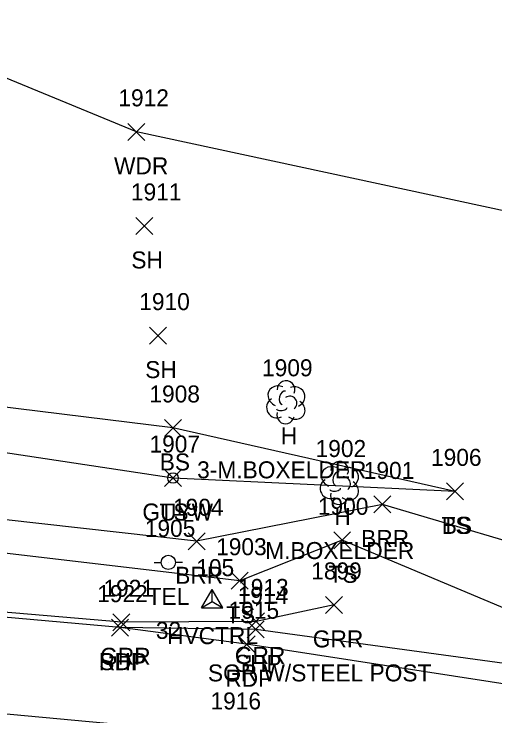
# Model space of a CAD drawing. Extents: x 1497084 to 1499861, y 734741 to 735567.
# Drawn here: x 1499623.4 to 1499680, y 735456.1 to 735538.6 of the extents above; entities that cross this region are included whole.
import ezdxf

# ---------------------------------------------------------------- set-up
doc = ezdxf.new("R2010")
doc.units = 0
for name, color, linetype in [('C_A', 7, 'Continuous'), ('C_I', 7, 'Continuous'), ('CPSM', 7, 'Continuous'), ('L_A', 7, 'Continuous'), ('L_C', 7, 'Continuous'), ('L_I', 7, 'Continuous'), ('L_TIC', 7, 'Continuous'), ('LABL', 7, 'Continuous'), ('LAWA', 7, 'Continuous'), ('LELB', 7, 'Continuous'), ('LTD', 7, 'Continuous'), ('P_A', 7, 'Continuous'), ('P_I', 7, 'Continuous'), ('P_TIC', 7, 'Continuous'), ('PET', 7, 'Continuous'), ('PRC', 7, 'Continuous'), ('PSP', 7, 'Continuous'), ('R_A', 7, 'Continuous'), ('R_C', 7, 'Continuous'), ('R_I', 7, 'Continuous'), ('R_TIC', 7, 'Continuous'), ('RGR', 7, 'Continuous'), ('U_A', 7, 'Continuous'), ('U_C', 7, 'Continuous'), ('U_I', 7, 'Continuous'), ('UP', 7, 'Continuous'), ('UPGW', 7, 'Continuous')]:
    doc.layers.add(name, color=color, linetype=linetype)

msp = doc.modelspace()

# ---------------------------------------------------------------- linework, layer by layer
at = {"layer": 'CPSM'}
for p, q in [((1499645.454, 735468.795), (1499646.704, 735470.96)), ((1499647.954, 735468.795), (1499646.704, 735470.96)), ((1499646.705, 735469.517), (1499646.704, 735470.96)), ((1499645.454, 735468.795), (1499646.705, 735469.517)), ((1499646.705, 735469.517), (1499646.705, 735469.517)), ((1499646.705, 735469.517), (1499647.954, 735468.795)), ((1499645.454, 735468.795), (1499647.954, 735468.795))]:
    msp.add_line(p, q, dxfattribs=at)
at = {"layer": 'L_TIC'}
for points in [[(1499636.791, 735523.775), (1499638.791, 735525.775)], [(1499638.791, 735523.775), (1499636.791, 735525.775)], [(1499637.702, 735512.707), (1499639.702, 735514.707)], [(1499639.702, 735512.707), (1499637.702, 735514.707)], [(1499639.338, 735499.808), (1499641.338, 735501.808)], [(1499641.338, 735499.808), (1499639.338, 735501.808)], [(1499641.088, 735488.947), (1499643.088, 735490.947)], [(1499643.088, 735488.947), (1499641.088, 735490.947)], [(1499641.096, 735483.057), (1499643.096, 735485.057)], [(1499643.096, 735483.057), (1499641.096, 735485.057)], [(1499674.288, 735481.485), (1499676.288, 735483.485)], [(1499676.288, 735481.485), (1499674.288, 735483.485)], [(1499674.288, 735481.485), (1499676.288, 735483.485)], [(1499676.288, 735481.485), (1499674.288, 735483.485)], [(1499665.752, 735479.946), (1499667.752, 735481.946)], [(1499667.752, 735479.946), (1499665.752, 735481.946)], [(1499643.867, 735475.617), (1499645.867, 735477.617)], [(1499645.867, 735475.617), (1499643.867, 735477.617)], [(1499661.005, 735475.729), (1499663.005, 735477.729)], [(1499663.005, 735475.729), (1499661.005, 735477.729)], [(1499648.942, 735470.977), (1499650.942, 735472.977)], [(1499650.942, 735470.977), (1499648.942, 735472.977)]]:
    msp.add_lwpolyline(points, dxfattribs=at)
at = {"layer": 'LABL'}
msp.add_lwpolyline([(1499689.554, 735474.192), (1499666.752, 735480.946), (1499644.867, 735476.617), (1499599.291, 735481.733), (1499595.722, 735488.498), (1499603.208, 735511.359), (1499612.735, 735535.087)], dxfattribs=at)
at = {"layer": 'LAWA'}
msp.add_lwpolyline([(1499788.738, 735496.153), (1499778.307, 735474.671), (1499770.599, 735459.37), (1499768.79, 735460.678), (1499758.938, 735469.149), (1499746.531, 735488.898), (1499729.211, 735490.085), (1499697.802, 735511.882), (1499637.791, 735524.775), (1499612.735, 735535.087), (1499594.485, 735538.631)], dxfattribs=at)
at = {"layer": 'LELB'}
for points in [[(1499675.288, 735482.485), (1499642.088, 735489.947), (1499602.834, 735494.783)], [(1499675.288, 735482.485), (1499642.096, 735484.057), (1499606.997, 735489.35)], [(1499770.599, 735459.37), (1499767.316, 735451.404), (1499753.266, 735453.514), (1499723.327, 735458.194), (1499688.043, 735465.791), (1499662.005, 735476.729), (1499649.942, 735471.977), (1499600.229, 735477.808), (1499596.973, 735472.366)]]:
    msp.add_lwpolyline(points, dxfattribs=at)
at = {"layer": 'LTD'}
for p, q in [((1499655.353, 735493.022), (1499655.353, 735493.022)), ((1499655.353, 735493.022), (1499655.353, 735493.022)), ((1499661.653, 735483.526), (1499661.653, 735483.526)), ((1499661.653, 735483.526), (1499661.653, 735483.526))]:
    msp.add_line(p, q, dxfattribs=at)
for centre in [(1499655.4, 735494.456), (1499661.699, 735484.96)]:
    msp.add_arc(centre, 1.047, 335.52715, 180.95627, dxfattribs=at)
for centre, major_axis, ratio, start_param, end_param in [((1499654.562, 735493.689), (1.21, -0.512), 0.895232, 1.570796, 4.712389), ((1499656.395, 735493.606), (-1.141, -0.483), 0.949671, 1.570796, 4.712389), ((1499655.145, 735493.481), (-0.208, -0.792), 0.645439, 3.141593, 6.283185), ((1499655.853, 735492.856), (-0.5, 0.667), 0.989748, 3.141593, 6.283185), ((1499654.27, 735492.314), (0.584, -1.042), 0.959034, 3.141593, 6.283185), ((1499656.354, 735492.189), (-1.09, 0.792), 0.841452, 1.570796, 4.712389), ((1499654.895, 735492.272), (-0.625, -0.083), 0.423636, 0, 3.141593), ((1499655.354, 735491.522), (0.265, 1.061), 0.942809, 1.570796, 4.712389), ((1499660.861, 735484.193), (1.21, -0.512), 0.895232, 1.570796, 4.712389), ((1499662.694, 735484.11), (-1.141, -0.483), 0.949671, 1.570796, 4.712389), ((1499661.444, 735483.985), (-0.208, -0.792), 0.645439, 3.141593, 6.283185), ((1499660.57, 735482.818), (0.584, -1.042), 0.959034, 3.141593, 6.283185), ((1499662.153, 735483.36), (-0.5, 0.667), 0.989748, 3.141593, 6.283185), ((1499662.653, 735482.693), (-1.09, 0.792), 0.841452, 1.570796, 4.712389), ((1499661.653, 735482.026), (0.265, 1.061), 0.942809, 1.570796, 4.712389), ((1499661.195, 735482.776), (-0.625, -0.083), 0.423636, 0, 3.141593)]:
    msp.add_ellipse(centre, major_axis=major_axis, ratio=ratio, start_param=start_param, end_param=end_param, dxfattribs=at)
at = {"layer": 'P_TIC'}
for points in [[(1499634.869, 735465.456), (1499636.869, 735467.456)], [(1499636.869, 735465.456), (1499634.869, 735467.456)], [(1499634.869, 735465.456), (1499636.869, 735467.456)], [(1499636.869, 735465.456), (1499634.869, 735467.456)], [(1499650.835, 735465.256), (1499652.835, 735467.256)], [(1499652.835, 735465.256), (1499650.835, 735467.256)], [(1499649.762, 735463.505), (1499651.762, 735465.505)], [(1499651.762, 735463.505), (1499649.762, 735465.505)]]:
    msp.add_lwpolyline(points, dxfattribs=at)
at = {"layer": 'PET'}
msp.add_lwpolyline([(1499846.488, 735425.23), (1499785.866, 735440.032), (1499753.42, 735446.608), (1499720.619, 735453.442), (1499687.533, 735458.833), (1499650.762, 735464.505), (1499635.869, 735466.456), (1499596.077, 735469.991)], dxfattribs=at)
at = {"layer": 'PRC'}
msp.add_lwpolyline([(1499843.886, 735414.074), (1499783.911, 735429.159), (1499752.36, 735435.285), (1499717.649, 735442.891), (1499685.251, 735447.999), (1499648.687, 735453.839), (1499595.43, 735458.808)], dxfattribs=at)
at = {"layer": 'PSP'}
msp.add_lwpolyline([(1499847.595, 735429.73), (1499789.267, 735443.962), (1499769.135, 735448.7), (1499753.081, 735451.309), (1499721.433, 735457.745), (1499687.714, 735461.331), (1499651.835, 735466.256), (1499635.869, 735466.456)], dxfattribs=at)
at = {"layer": 'R_TIC'}
for points in [[(1499660.063, 735468.133), (1499662.063, 735470.133)], [(1499662.063, 735468.133), (1499660.063, 735470.133)], [(1499635.029, 735466.086), (1499637.029, 735468.086)], [(1499637.029, 735466.086), (1499635.029, 735468.086)], [(1499650.881, 735466.189), (1499652.881, 735468.189)], [(1499652.881, 735466.189), (1499650.881, 735468.189)]]:
    msp.add_lwpolyline(points, dxfattribs=at)
at = {"layer": 'RGR'}
msp.add_lwpolyline([(1499661.063, 735469.133), (1499651.881, 735467.189), (1499636.029, 735467.086), (1499596.371, 735470.478)], dxfattribs=at)
at = {"layer": 'UP'}
for p, q in [((1499639.886, 735474.132), (1499640.712, 735474.132)), ((1499641.545, 735474.137), (1499641.545, 735474.137)), ((1499643.212, 735474.137), (1499642.379, 735474.137)), ((1499642.379, 735474.137), (1499642.379, 735474.137)), ((1499643.212, 735474.137), (1499643.212, 735474.137))]:
    msp.add_line(p, q, dxfattribs=at)
msp.add_circle((1499641.545, 735474.137), 0.833, dxfattribs=at)
at = {"layer": 'UPGW'}
for radius in [0.625, 0.0833]:
    msp.add_circle((1499642.096, 735484.057), radius, dxfattribs=at)

# ---------------------------------------------------------------- texts
at = {"layer": 'C_A'}
msp.add_text('HVCTRL', height=2, dxfattribs=at).set_placement((1499641.398, 735464.517))
at = {"layer": 'C_I'}
msp.add_text('105', height=2, dxfattribs=at).set_placement((1499644.831, 735472.517))
at = {"layer": 'L_A'}
for s, p in [('WDR', (1499635.153, 735519.775)), ('SH', (1499637.19, 735508.707)), ('SH', (1499638.826, 735495.808)), ('H', (1499654.787, 735488.022)), ('BS', (1499640.529, 735484.947)), ('TS', (1499640.506, 735479.057)), ('H', (1499661.086, 735478.526)), ('TS', (1499673.698, 735477.485)), ('BS', (1499673.729, 735477.485)), ('BRR', (1499664.24, 735475.946)), ('BRR', (1499642.355, 735471.617)), ('TS', (1499660.414, 735471.729)), ('TS', (1499648.351, 735466.977))]:
    msp.add_text(s, height=2, dxfattribs=at).set_placement(p)
at = {"layer": 'L_C'}
for s, p in [('3-M.BOXELDER', (1499644.936, 735484.022)), ('M.BOXELDER', (1499652.952, 735474.526))]:
    msp.add_text(s, height=2, dxfattribs=at).set_placement(p)
at = {"layer": 'L_I'}
for s, p in [('1912', (1499635.665, 735527.775)), ('1911', (1499637.143, 735516.707)), ('1910', (1499638.125, 735503.808)), ('1909', (1499652.574, 735496.022)), ('1908', (1499639.316, 735492.947)), ('1907', (1499639.325, 735487.057)), ('1902', (1499658.881, 735486.526)), ('1906', (1499672.462, 735485.485)), ('1906', (1499672.462, 735485.485)), ('1901', (1499664.547, 735483.946)), ('1904', (1499642.096, 735479.617)), ('1900', (1499659.147, 735479.729)), ('1903', (1499647.17, 735474.977))]:
    msp.add_text(s, height=2, dxfattribs=at).set_placement(p)
at = {"layer": 'P_A'}
for s, p in [('SHP', (1499633.405, 735461.456)), ('RDP', (1499633.357, 735461.456)), ('SHP', (1499649.371, 735461.256)), ('RDP', (1499648.251, 735459.505))]:
    msp.add_text(s, height=2, dxfattribs=at).set_placement(p)
at = {"layer": 'P_I'}
for s, p in [('1922', (1499633.176, 735469.456)), ('1922', (1499633.176, 735469.456)), ('1914', (1499649.709, 735469.256)), ('1915', (1499648.636, 735467.505)), ('1916', (1499646.506, 735456.839))]:
    msp.add_text(s, height=2, dxfattribs=at).set_placement(p)
at = {"layer": 'R_A'}
for p in [(1499658.551, 735464.133), (1499633.517, 735462.086), (1499649.37, 735462.189)]:
    msp.add_text('GRR', height=2, dxfattribs=at).set_placement(p)
at = {"layer": 'R_C'}
msp.add_text('SGR W/STEEL POST', height=2, dxfattribs=at).set_placement((1499646.205, 735460.133))
at = {"layer": 'R_I'}
for s, p in [('1899', (1499658.362, 735472.133)), ('1913', (1499649.756, 735470.189)), ('1921', (1499633.903, 735470.086))]:
    msp.add_text(s, height=2, dxfattribs=at).set_placement(p)
at = {"layer": 'U_A'}
for s, p in [('GUYW', (1499638.49, 735479.057)), ('TEL', (1499639.105, 735469.137))]:
    msp.add_text(s, height=2, dxfattribs=at).set_placement(p)
at = {"layer": 'U_C'}
msp.add_text('32', height=2, dxfattribs=at).set_placement((1499640.081, 735465.137))
at = {"layer": 'U_I'}
for s, p in [('1907', (1499639.325, 735487.057)), ('1905', (1499638.774, 735477.137))]:
    msp.add_text(s, height=2, dxfattribs=at).set_placement(p)

doc.saveas('drawing.dxf')
